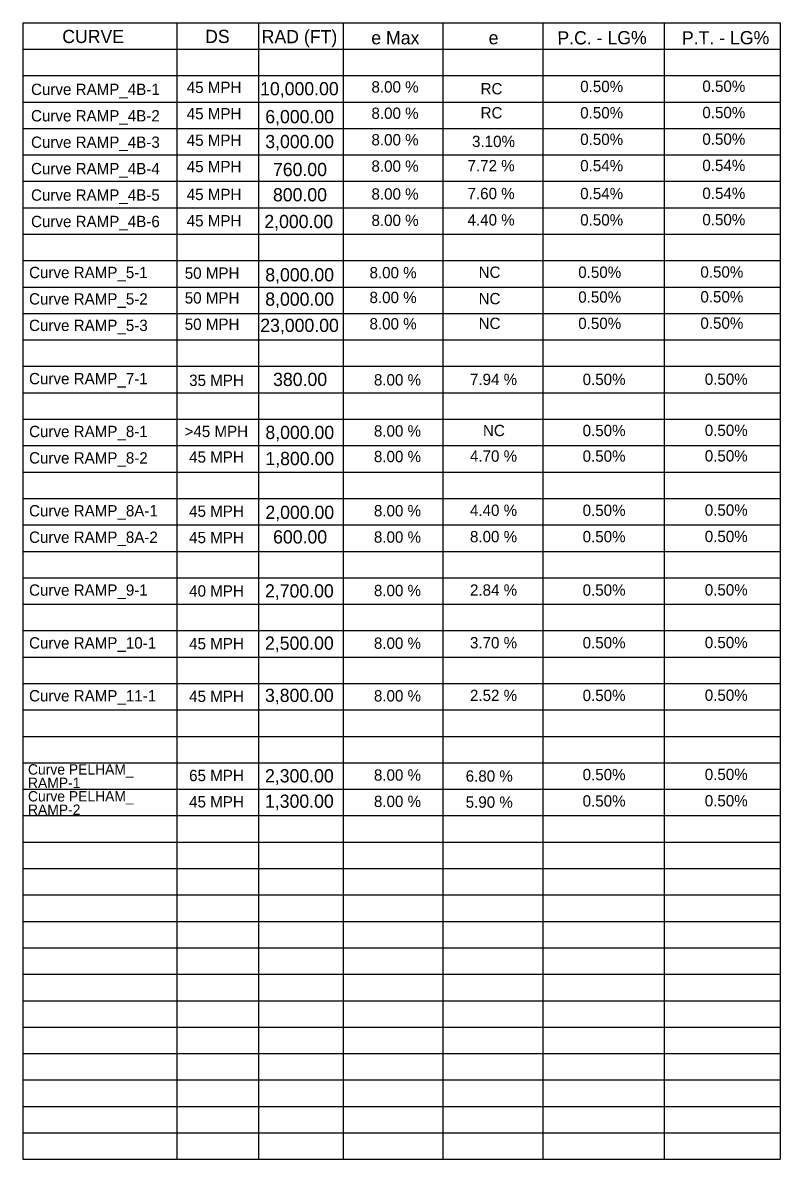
# Model space of a CAD drawing. Extents: x 1609180 to 1612299, y 1092317 to 1096201.
# Drawn here: x 1610590 to 1610991, y 1095436 to 1096038 of the extents above; entities that cross this region are included whole.
import ezdxf

# ---------------------------------------------------------------- set-up
doc = ezdxf.new("R2010")
doc.units = 0
doc.layers.add('RD_HC_Data_50', color=7, linetype='Continuous')
doc.layers.add('RD_SHT_TX', color=7, linetype='Continuous')

msp = doc.modelspace()

# ---------------------------------------------------------------- linework, layer by layer
at = {"layer": 'RD_SHT_TX'}
for p, q in [((1610589.82, 1096037.78), (1610991.27, 1096037.78)), ((1610589.82, 1096037.78), (1610589.82, 1095435.78)), ((1610671.45, 1096037.78), (1610671.45, 1095435.78)), ((1610714.81, 1096037.78), (1610714.81, 1095435.78)), ((1610759.58, 1096037.78), (1610759.58, 1095435.78)), ((1610812.48, 1096037.78), (1610812.48, 1095435.78)), ((1610865.38, 1096037.78), (1610865.38, 1095435.78)), ((1610929.76, 1096037.78), (1610929.76, 1095435.78)), ((1610991.27, 1096037.78), (1610991.27, 1095435.78)), ((1610589.82, 1096023.78), (1610991.27, 1096023.78)), ((1610589.82, 1096009.78), (1610991.27, 1096009.78)), ((1610589.82, 1095995.78), (1610991.27, 1095995.78)), ((1610589.82, 1095981.78), (1610991.27, 1095981.78)), ((1610589.82, 1095967.78), (1610991.27, 1095967.78)), ((1610589.82, 1095953.78), (1610991.27, 1095953.78)), ((1610589.82, 1095939.78), (1610991.27, 1095939.78)), ((1610589.82, 1095925.78), (1610991.27, 1095925.78)), ((1610589.82, 1095911.78), (1610991.27, 1095911.78)), ((1610589.82, 1095897.78), (1610991.27, 1095897.78)), ((1610589.82, 1095883.78), (1610991.27, 1095883.78)), ((1610589.82, 1095869.78), (1610991.27, 1095869.78)), ((1610589.82, 1095855.78), (1610991.27, 1095855.78)), ((1610589.82, 1095841.78), (1610991.27, 1095841.78)), ((1610589.82, 1095827.78), (1610991.27, 1095827.78)), ((1610589.82, 1095813.78), (1610991.27, 1095813.78)), ((1610589.82, 1095799.78), (1610991.27, 1095799.78)), ((1610589.82, 1095785.78), (1610991.27, 1095785.78)), ((1610589.82, 1095771.78), (1610991.27, 1095771.78)), ((1610589.82, 1095757.78), (1610991.27, 1095757.78)), ((1610589.82, 1095743.78), (1610991.27, 1095743.78)), ((1610589.82, 1095729.78), (1610991.27, 1095729.78)), ((1610589.82, 1095715.78), (1610991.27, 1095715.78)), ((1610589.82, 1095701.78), (1610991.27, 1095701.78)), ((1610589.82, 1095687.78), (1610991.27, 1095687.78)), ((1610589.82, 1095673.78), (1610991.27, 1095673.78)), ((1610589.82, 1095659.78), (1610991.27, 1095659.78)), ((1610589.82, 1095645.78), (1610991.27, 1095645.78)), ((1610589.82, 1095631.78), (1610991.27, 1095631.78)), ((1610589.82, 1095617.78), (1610991.27, 1095617.78)), ((1610589.82, 1095603.78), (1610991.27, 1095603.78)), ((1610589.82, 1095589.78), (1610991.27, 1095589.78)), ((1610589.82, 1095575.78), (1610991.27, 1095575.78)), ((1610589.82, 1095561.78), (1610991.27, 1095561.78)), ((1610589.82, 1095547.78), (1610991.27, 1095547.78)), ((1610589.82, 1095533.78), (1610991.27, 1095533.78)), ((1610589.82, 1095519.78), (1610991.27, 1095519.78)), ((1610589.82, 1095505.78), (1610991.27, 1095505.78)), ((1610589.82, 1095491.78), (1610991.27, 1095491.78)), ((1610589.82, 1095477.78), (1610991.27, 1095477.78)), ((1610589.82, 1095463.78), (1610991.27, 1095463.78)), ((1610589.82, 1095449.78), (1610991.27, 1095449.78)), ((1610589.82, 1095435.78), (1610991.27, 1095435.78))]:
    msp.add_line(p, q, dxfattribs=at)

# ---------------------------------------------------------------- texts
at = {"layer": 'RD_HC_Data_50'}
for s, p in [('P.C. - LG%', (1610873.17, 1096026.23)), ('P.T. - LG%', (1610939.15, 1096026.23))]:
    msp.add_text(s, height=7, rotation=0.2225, dxfattribs=at).set_placement(p)
for s, p in [('0.50%', (1610949.98, 1096001.14)), ('45 MPH', (1610676.73, 1096000.56)), ('8.00 %', (1610774.63, 1096000.79)), ('RC', (1610832.44, 1095999.83)), ('0.50%', (1610885.25, 1096001.03)), ('45 MPH', (1610676.73, 1095986.61)), ('8.00 %', (1610774.63, 1095986.84)), ('RC', (1610832.44, 1095987.08)), ('0.50%', (1610885.25, 1095987.08)), ('0.50%', (1610949.98, 1095987.2)), ('45 MPH', (1610676.73, 1095972.56)), ('8.00 %', (1610774.63, 1095972.79)), ('3.10%', (1610827.93, 1095971.93)), ('0.50%', (1610885.25, 1095973.03)), ('0.50%', (1610949.98, 1095973.14)), ('7.72 %', (1610825.54, 1095959.08)), ('0.54%', (1610885.25, 1095959.08)), ('0.54%', (1610949.98, 1095959.2)), ('45 MPH', (1610676.73, 1095958.61)), ('8.00 %', (1610774.63, 1095958.84)), ('45 MPH', (1610676.73, 1095943.84)), ('8.00 %', (1610774.63, 1095944.08)), ('7.60 %', (1610825.54, 1095944.31)), ('0.54%', (1610885.25, 1095944.31)), ('0.54%', (1610949.98, 1095944.43)), ('45 MPH', (1610676.73, 1095929.89)), ('8.00 %', (1610774.63, 1095930.13)), ('4.40 %', (1610825.54, 1095930.36)), ('0.50%', (1610885.25, 1095930.36)), ('0.50%', (1610949.98, 1095930.48)), ('50 MPH', (1610675.69, 1095902.16)), ('8.00 %', (1610773.59, 1095902.39)), ('NC', (1610831.4, 1095902.63)), ('0.50%', (1610884.21, 1095902.63)), ('0.50%', (1610948.94, 1095902.75)), ('50 MPH', (1610675.69, 1095889.03)), ('8.00 %', (1610773.59, 1095889.27)), ('NC', (1610831.4, 1095888.63)), ('0.50%', (1610884.21, 1095889.5)), ('0.50%', (1610948.94, 1095889.62)), ('50 MPH', (1610675.69, 1095875.08)), ('8.00 %', (1610773.59, 1095875.32)), ('NC', (1610831.4, 1095875.55)), ('0.50%', (1610884.21, 1095875.55)), ('0.50%', (1610948.94, 1095875.67)), ('35 MPH', (1610678.01, 1095845.39)), ('8.00 %', (1610775.92, 1095845.63)), ('7.94 %', (1610826.83, 1095845.86)), ('0.50%', (1610886.53, 1095845.86)), ('0.50%', (1610951.26, 1095845.98)), ('>45 MPH', (1610675.57, 1095818.32)), ('8.00 %', (1610775.92, 1095818.55)), ('NC', (1610833.72, 1095818.79)), ('0.50%', (1610886.53, 1095818.79)), ('0.50%', (1610951.26, 1095818.9)), ('45 MPH', (1610678.01, 1095804.78)), ('8.00 %', (1610775.92, 1095805.01)), ('4.70 %', (1610826.83, 1095805.25)), ('0.50%', (1610886.53, 1095805.25)), ('0.50%', (1610951.26, 1095805.36)), ('45 MPH', (1610678.01, 1095776.06)), ('8.00 %', (1610775.92, 1095776.3)), ('4.40 %', (1610826.83, 1095776.53)), ('0.50%', (1610886.53, 1095776.53)), ('0.50%', (1610951.26, 1095776.65)), ('45 MPH', (1610678.01, 1095762.11)), ('8.00 %', (1610775.92, 1095762.35)), ('8.00 %', (1610826.83, 1095762.58)), ('0.50%', (1610886.53, 1095762.58)), ('0.50%', (1610951.26, 1095762.7)), ('40 MPH', (1610678.01, 1095733.81)), ('8.00 %', (1610775.92, 1095734.04)), ('2.84 %', (1610826.83, 1095734.28)), ('0.50%', (1610886.53, 1095734.28)), ('0.50%', (1610951.26, 1095734.39)), ('3.70 %', (1610826.83, 1095706.38)), ('0.50%', (1610886.53, 1095706.38)), ('0.50%', (1610951.26, 1095706.5)), ('45 MPH', (1610678.01, 1095705.91)), ('8.00 %', (1610775.92, 1095706.14)), ('45 MPH', (1610678.01, 1095678.01)), ('8.00 %', (1610775.92, 1095678.25)), ('2.52 %', (1610826.83, 1095678.48)), ('0.50%', (1610886.53, 1095678.48)), ('0.50%', (1610951.26, 1095678.6)), ('65 MPH', (1610678.01, 1095636.06)), ('8.00 %', (1610775.92, 1095636.3)), ('0.50%', (1610886.53, 1095636.53)), ('0.50%', (1610951.26, 1095636.65)), ('45 MPH', (1610678.01, 1095622.11)), ('8.00 %', (1610775.92, 1095622.35)), ('0.50%', (1610886.53, 1095622.58)), ('0.50%', (1610951.26, 1095622.7))]:
    msp.add_text(s, height=6, dxfattribs=at).set_placement(p)
at = {"layer": 'RD_SHT_TX'}
for s, height, p in [('CURVE', 7, (1610610.77, 1096027.01)), ('DS', 7, (1610686.47, 1096027.04)), ('RAD (FT)', 7, (1610716.46, 1096026.9)), ('e Max', 7, (1610774.54, 1096026.33)), ('e', 7, (1610836.72, 1096026.33)), ('Curve RAMP_4B-1', 6, (1610594.23, 1095999.5)), ('10,000.00', 7, (1610715.63, 1095999.34)), ('Curve RAMP_4B-2', 6, (1610594.23, 1095985.5)), ('6,000.00', 7, (1610718.35, 1095984.55)), ('Curve RAMP_4B-3', 6, (1610594.23, 1095971.5)), ('3,000.00', 7, (1610718.35, 1095971.34)), ('Curve RAMP_4B-4', 6, (1610594.23, 1095957.5)), ('760.00', 7, (1610722.43, 1095956.55)), ('Curve RAMP_4B-5', 6, (1610594.23, 1095943.5)), ('800.00', 7, (1610722.43, 1095943.17)), ('Curve RAMP_4B-6', 6, (1610594.23, 1095929.5)), ('2,000.00', 7, (1610717.86, 1095929)), ('Curve RAMP_5-1             ', 6, (1610593.19, 1095902.49)), ('8,000.00', 7, (1610718.35, 1095900.78)), ('Curve RAMP_5-2             ', 6, (1610593.19, 1095888.49)), ('8,000.00', 7, (1610718.35, 1095887.89)), ('23,000.00', 7, (1610715.7, 1095873.98)), ('Curve RAMP_5-3             ', 6, (1610593.19, 1095874.49)), ('Curve RAMP_7-1             ', 6, (1610593.19, 1095846.28)), ('380.00', 7, (1610722.5, 1095845.36)), ('Curve RAMP_8-1             ', 6, (1610593.19, 1095818.28)), ('8,000.00', 7, (1610718.42, 1095817.28)), ('Curve RAMP_8-2             ', 6, (1610593.19, 1095804.28)), ('1,800.00', 7, (1610718.42, 1095803.45)), ('Curve RAMP_8A-1            ', 6, (1610593.19, 1095776.28)), ('2,000.00', 7, (1610718.42, 1095774.96)), ('Curve RAMP_8A-2            ', 6, (1610593.19, 1095762.28)), ('600.00', 7, (1610722.5, 1095761.94)), ('Curve RAMP_9-1             ', 6, (1610593.19, 1095734.28)), ('2,700.00', 7, (1610718.2, 1095733.34)), ('Curve RAMP_10-1            ', 6, (1610593.19, 1095706.28)), ('2,500.00', 7, (1610718.2, 1095705.67)), ('Curve RAMP_11-1            ', 6, (1610593.19, 1095678.28)), ('3,800.00', 7, (1610718.2, 1095678)), ('Curve PELHAM_', 5.5, (1610592.6, 1095639.52)), ('2,300.00', 7, (1610718.2, 1095635.39)), ('6.80 %', 6, (1610824.56, 1095635.77)), ('RAMP-1', 5.5, (1610592.6, 1095632.4)), ('Curve PELHAM_', 5.5, (1610592.6, 1095625.3)), ('1,300.00', 7, (1610718.2, 1095621.96)), ('5.90 %', 6, (1610824.56, 1095621.97)), ('RAMP-2', 5.5, (1610592.6, 1095618.18))]:
    msp.add_text(s, height=height, dxfattribs=at).set_placement(p)

doc.saveas('drawing.dxf')
